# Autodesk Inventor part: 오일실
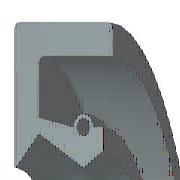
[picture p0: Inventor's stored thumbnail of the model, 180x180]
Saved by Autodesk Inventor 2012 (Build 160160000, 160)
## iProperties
IsCustomPart: 0
Created: 2009-02
Part Number: 오일실
Material: 고무
Description: 오일-실
Document SubType Name: Modeling
Standard: KS B 2804
Designer: KYOUNG IL JANG
Standards Organization: KS
Language: ko-KR
Size Designation: D - 20 32 8
Categories: <MemberInstance><Categories><Category DisplayName="샤프트 부품" InternalName="7f7aeb1f-a693-4053-b835-cee3144e0d98" Mnemonic="SHFT"><Category DisplayName="실링" Intern
Density: 0.93 g/cm^3
Mass: 2.19344 g
Surface Area: 31.4782 cm^2
Volume: 2.35853 cm^3
Author: KYOUNG IL JANG
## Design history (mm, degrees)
revolve "본체" stored, may be unused: angle "d17" = 90 deg
revolve "스프링1" stored, may be unused: angle "d18" = 90 deg
body "Solid1"
sketch "스케치1"
  geometry: L1 (0, 16)-(8, 16); L2 (8, 14.25)-(1.75, 14.25); L3 (1.75, 11.75)-(4.9, 10); L4 (4.9, 10)-(0, 10); L5 (0, 0)-(9.586, 0) reference; L6 (4.9, 10)-(6.3, 10.875); L7 (0, 18)-(0, -3) reference; L8 (-1.941, 0)-(11.507, 0) reference; L9 (4.2, 12.1)-(1.75, 12.71); L10 (1.75, 12.71)-(1.75, 14.25); L11 (0, 16)-(0, 10.088); L12 (4.9, 10)-(0, 10); L13 (1.75, 11.75)-(0.152, 10.028); L14 (8, 16)-(8, 14.25); L15 (5.6, 12.1)-(6.3, 12.1); L16 (6.3, 12.1)-(6.3, 10.875); C1 r 0.455 at (4.9, 12.1); A1 r 0.7 centre (4.9, 12.1) between (5.6, 12.1) and (4.2, 12.1); A2 r 0.088 centre (0.088, 10.088) between (0, 10.088) and (0.152, 10.028); 1 further point
  constraints: 28 end point, 5 horizontal alignment, 5 point on line, 4 point on circle, 4 vertical alignment, 3 centre point, 3 tangent, 2 collinear, 2 horizontal, 2 perpendicular, 1 coincident, 1 parallel
  dimensions: "d0" = 32 diameter of L1 L5 (= SD2); "d1" = 1.75 distance of L1.end L2.start (= SD); "d2" = 0.91 diameter of C1 (= SPDI); "d3" = 1.4 diameter of A1 (= SPDA); "d4" = 20 diameter of L3.end L5 (= NND); "d5" = 23.5 diameter of L3.start L5 (= TKDM); "d7" = 25.42 diameter of L9.end L5 (= TKDM + 0.24 x SWDT); "d8" = 1.75 distance between parallel lines of L11 L10 (= SD); "d9" = 4.9 distance from line of L11 C1.centre (= SPDST); "d10" = 24.2 diameter of C1.centre L5 (= HLDM); "d11" = 0.0875 radius of A2 (= 0.25 x LAB); "d12" = 6.3 distance between parallel lines of L11 L16 (= SDI); "d13" = 21.75 diameter of L6.end L5 (= ABDM); "d14" = 8 distance from line of L11 L1.end (= SWDT)
fillet "모깎기1" dims "d6" = 0.3 (= RR)
other parameters: "SD2" = 32 [user parameter; used in 1 equation term], "SWDT" = 8 [user parameter; used in 2 equation terms], "RR" = 0.3 [user parameter; used in 1 equation term], "SD" = 1.75 [user parameter; used in 2 equation terms], "NND" = 20 [user parameter; used in 1 equation term], "SPDA" = 1.4 [user parameter; used in 1 equation term], "SPDI" = 0.91 [user parameter; used in 1 equation term], "TKDM" = 23.5 [user parameter; used in 2 equation terms], "HLDM" = 24.2 [user parameter; used in 1 equation term], "ABDM" = 21.75 [user parameter; used in 1 equation term], "SDI" = 6.3 [user parameter; used in 1 equation term], "SPDST" = 4.9 [user parameter; used in 1 equation term], "LAB" = 0.35 [user parameter; used in 1 equation term], "d15" = 0, "d16" = 0, "d19" = 0
